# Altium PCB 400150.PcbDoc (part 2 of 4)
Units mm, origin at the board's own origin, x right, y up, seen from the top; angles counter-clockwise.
Board outline 101.6 x 63.5 mm, 4 copper layers (Top Layer, Mid-Layer 1, Mid-Layer 2, Bottom Layer), stack 1.582 mm thick; 248 components, 179 nets, 1093 pads, 875 vias.
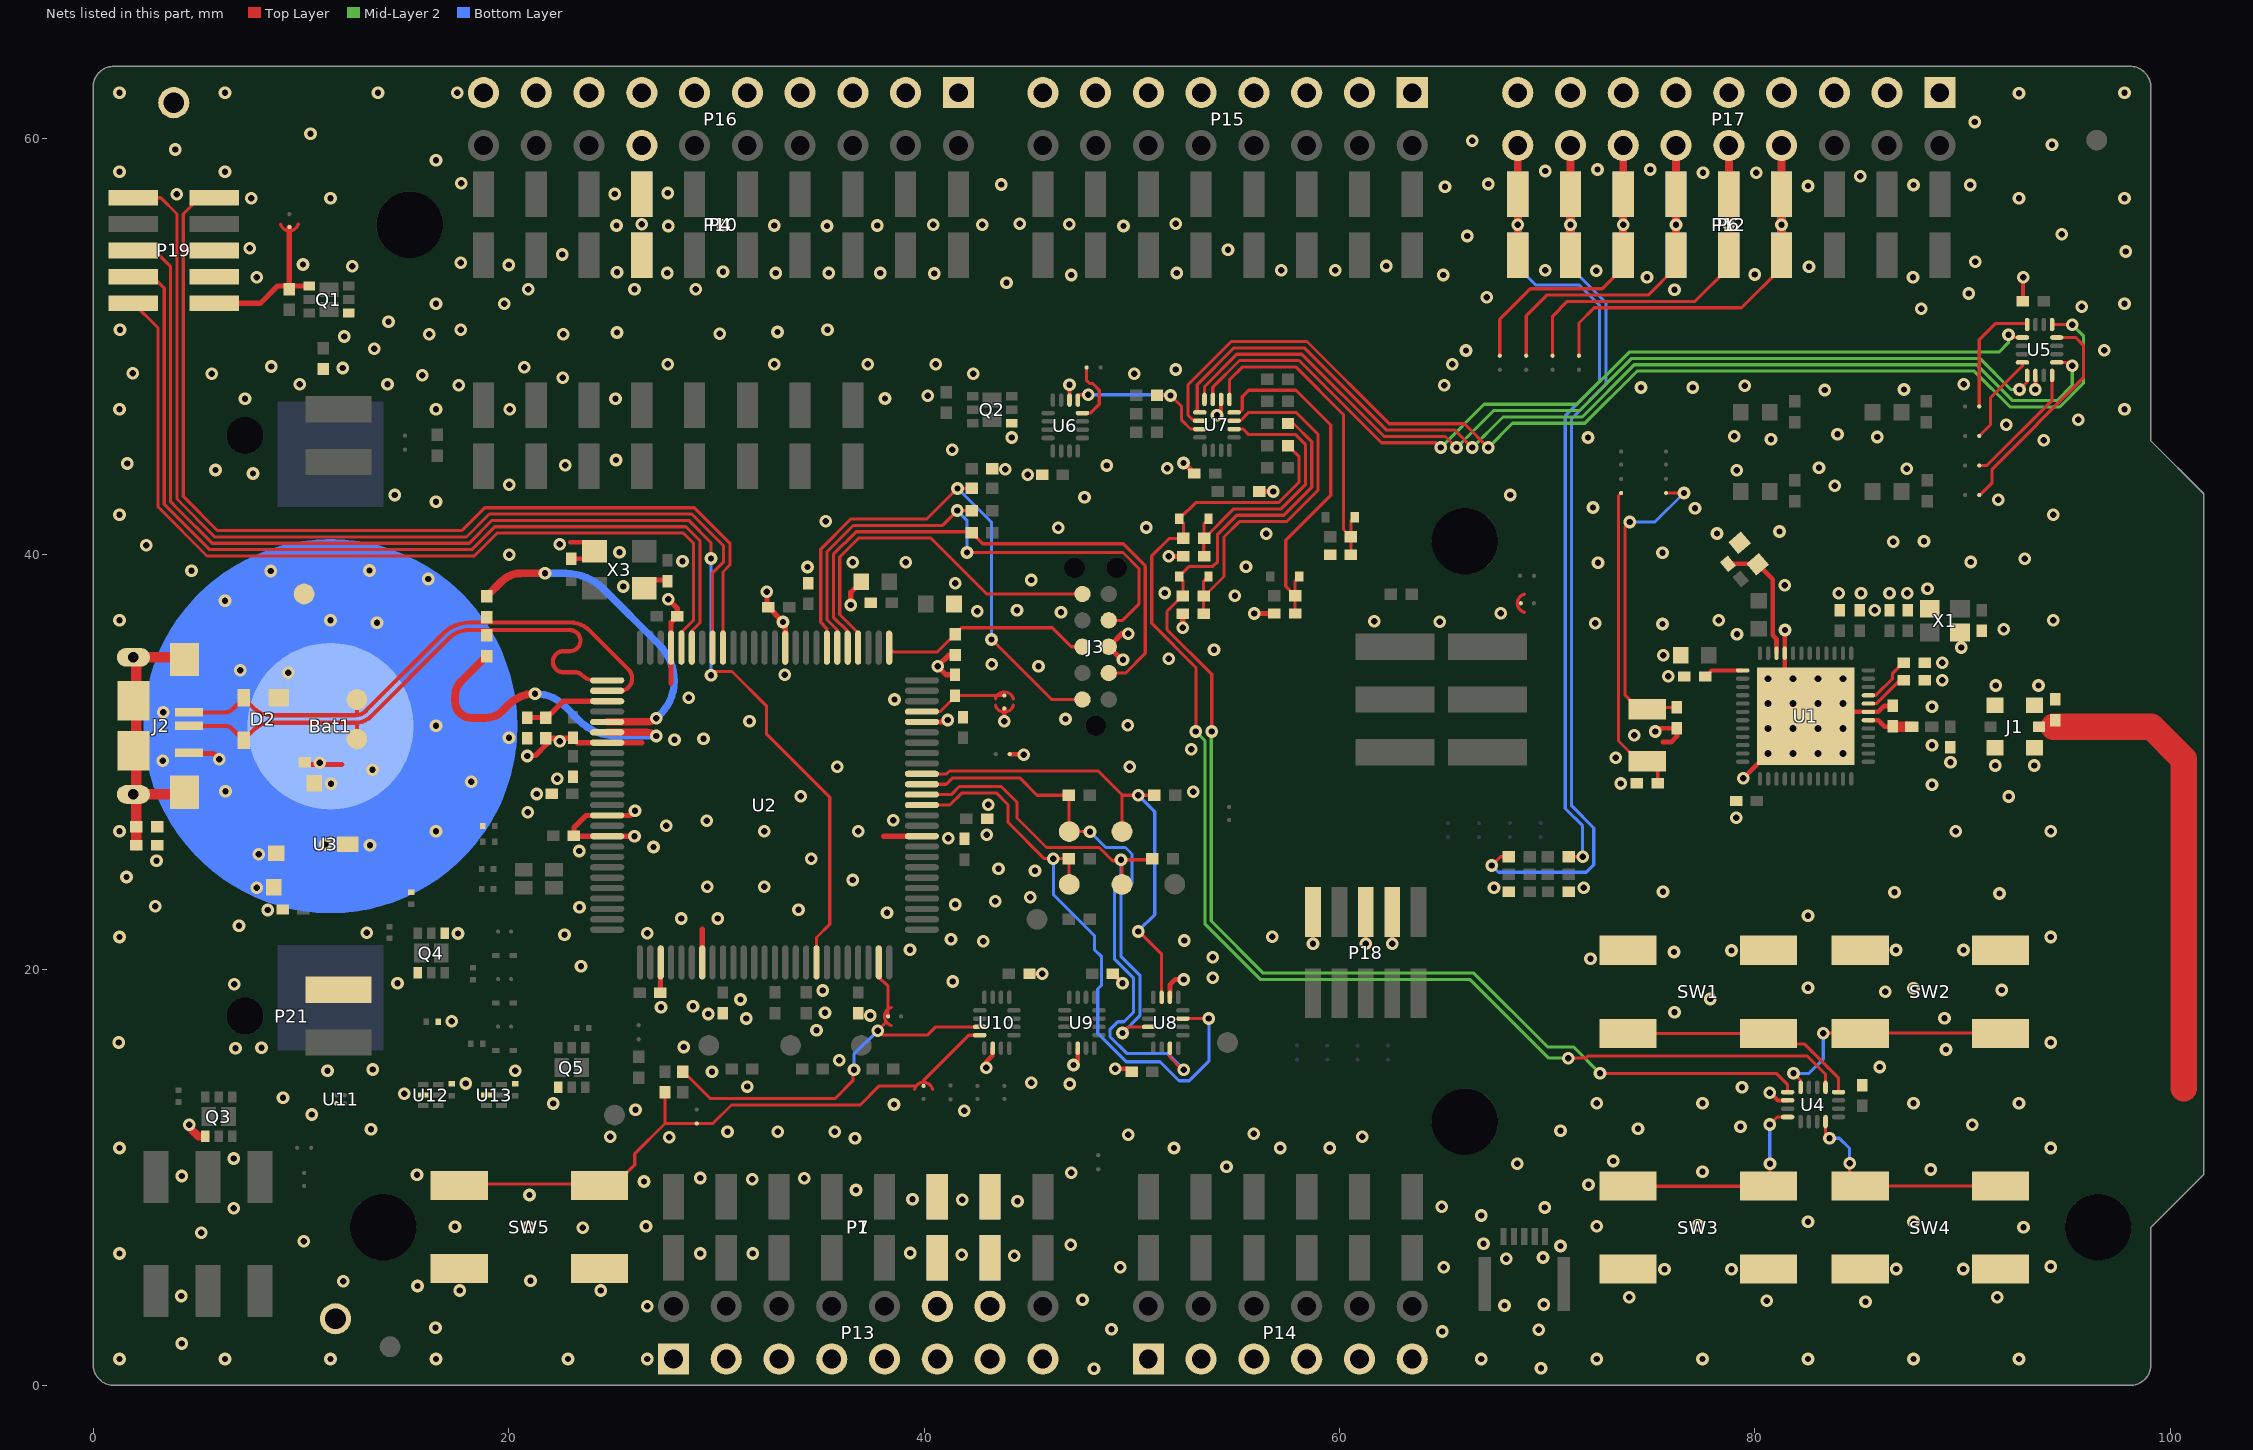
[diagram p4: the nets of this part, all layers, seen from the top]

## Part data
Bat1: library part "Bat Holder CR2032 SMD", "Bat Holder CR2032 SMD", 2nd source part number=165-0693, Manufacturer=Comfortable, Manufacturer Part Number=BC-2001, Supplier part number="BC-2001/T & R"
C1 C2 C11 C12 C52 C53: library part C0402-12p, "Capacitor, NP0, ±2%", Part number IPS=00000002398
C3: library part C0402-0.8p, "Capacitor, NP0, ±5%", Part number IPS=00000007782
C4 C5 C8 C14 C18 C19 C21 C24 C25 C26 C27 C28 C29 C32 C34 C35 C36 C38 C39 C40 C41 C44 C45 C46 C47 C54 C55: library part C0402-100n, "Capacitor, X7R, ±10%", Part number IPS=00000005296
C6 C13: library part C0402-N.C., "Not mounted"
C7: library part C0402-100p, "Capacitor, NP0, ±5%", Part number IPS=00000002361
C9: library part C0603-4µ7, "Capacitor, X5R, ±10%", Part number IPS=00000007783
C10 C16 C17: library part C0603-1µ0, "Capacitor, X7R, ±10%", Part number IPS=00000000616
C15: library part C0402-1.2p, "Capacitor, NP0, ±0.1pF", Part number IPS=00000005410
C20 C31 C33: library part C0603-10µ, "Capacitor, X5R, ±20%", Part number IPS=00000007785
C22 C23: library part C0402-18p, "Capacitor, NP0, ±5%"
C30: library part C0402-10n, "Capacitor, X7R, ±10%", Part number IPS=00000007784
C37: library part C0402-10p, "Capacitor, NP0, ±2%", 2nd source part number=185-6064, Supplier part number=712-1252-1-ND
C42 C43: library part C0402-300p, "Capacitor, NP0, ±5%", Supplier part number=490-3234-1-ND
C48 C49 C50 C51: library part C0402-1µ0, "Capacitor, X5R, ±5%", Part number IPS=00000007786, Supplier part number=1276-1444-1-ND
C56 C57: library part C0201-100n, "Capacitor, X5R, ±10%", Part number IPS=00000001248
D1 D7 D8: "20V schottky barrier diode, Vf 350 mV @ 100 mA, Ir 2.0 µA @ 10 V, If 500 mA", Manufacturer="ON Semiconductor", Part number IPS=N.A., Supplier Part Number 1=NSR0620P2T5GOSCT-ND
D2: "Ultra low capacitance double rail-to-rail ESD protection diode", 2nd source part number=152-4157, Manufacturer=NXP, Supplier part number=568-4140-1-ND
D3 D4 D5 D6: "Diode Schottky Vf=0.38, Vr=40V, If=200mA, Ir=500nA", 2nd source part number=873-4097, Manufacturer=NXP, Supplier part number=568-5973-1-ND
Fid1 Fid2: library part Fid-Mark, "Fiducial Mark"
J1: "Coaxial Connector with Switch", 2nd source part number=81-MM8130-2600RA2, Manufacturer=Murata, Supplier part number=490-4981-1-ND
J2: library part USB-Micro-B-RA-SMD-PiP, "MicroUSB-B-SMT", 2nd source part number=609-4616-1-ND, Manufacturer="Allen Creations Corp.", Manufacturer Part Number=AJU55-BS2111-L, Part number IPS=00000007790
J3: library part TC2050-IDC-NLFP, "CBL PLUG-OF-NAILS 10-PIN", Manufacturer="Tag-Connect LLC", Supplier part number=TC2050-IDC-NL-ND
L1: library part L0402-3n9, "Inductor, 170mA, ±0.1nH", Manufacturer=Murata, Manufacturer Part Number=LQP15MN3N9B02D, Part number IPS=00000007793, Supplier part number=490-1131-1-ND
L2: library part L0603-10µ, "Inductor, 80mA, ±10%", 2nd source part number=178-6105, Manufacturer="Taiyo Yuden", Manufacturer Part Number=LBMF1608T100K, Part number IPS=00000007794, Supplier part number=587-1714-1-ND
L3: library part L0402-15n, "Inductor, 320mA, ±5%", 2nd source part number=658-1328, Manufacturer="Taiyo Yuden", Manufacturer Part Number=HK100515NJ-T, Part number IPS=00000003215, Supplier part number=587-1521-1-ND
LD5: library part LTST-C195KGJRKT, "Ultra bright AlInGaP Bi-Color LED", 2nd source part number=859-LTST-C195KGJRKT, Manufacturer="Lite-On Inc", Supplier part number=160-1452-1-ND
LED1 LED2 LED3 LED4: library part "LG L29K Smartled Green", "LED SMARTLED GREEN 570NM 0603", 2nd source part number=720-LGL29KG2J124Z, Manufacturer=Osram, Manufacturer Part Number="LG L29K-G2J1-24-Z", Supplier part number=475-2709-1-ND
P1 P3: library part "Socket 1x8 SMD", "Socket 1x8, 2.54mm (100mil), SMD", 2nd source part number=SSM-108-F-SV-P-TR, Manufacturer=W-CON, Manufacturer Part Number=2171-108MS0CUNR1
P2: library part "Socket 1x6 SMD", "Socket 1x6, 2.54mm (100mil), SMD", 2nd source part number=SSM-106-F-SV-P-TR, Manufacturer=W-CON, Manufacturer Part Number=2171-106MS0CUNR1
P4: library part "Socket 1x10 SMD", "Socket 1x10, 2.54mm (100mil), SMD", 2nd source part number=SSM-110-F-SV-P-TR, Manufacturer=W-CON, Manufacturer Part Number=2171-110MS0CUNR1
P5: library part "Pin Header 2x3 SMD", "Pin Header 2x3, 2.54mm (100mil) SMD", 2nd source part number=TSM-103-01-L-DV, Manufacturer=W-CON, Manufacturer Part Number=1125-1203S0M116R1
P6: library part "Socket 1x9 SMD", "Socket 1x9, 2.54mm (100mil), SMD", 2nd source part number=SSM-109-L-SV, Manufacturer=W-CON, Manufacturer Part Number=2171-109MS0CUNR1
P7 P9: library part "Pin List 1x8 SMD, N.C.", "Pin List 1x8, 2.54mm (100mil), SMD", Manufacturer=W-CON, Manufacturer Part Number=1125-1108S0M116R2, Part number IPS=N.A.
P8: library part "Pin List 1x6 SMD, N.C.", "Pin List 1x6, 2.54mm (100mil), SMD", Manufacturer=W-CON, Manufacturer Part Number=1125-1106S0M116R2, Part number IPS=N.A.
P10: library part "Pin List 1x10 SMD, N.C.", "Pin List 1x10, 2.54mm (100mil), SMD", Manufacturer=W-CON, Manufacturer Part Number=1125-1110S0M116R2, Part number IPS=N.A.
P11: library part "Socket 2x3 SMD Bottom, N.C.", "Socket 2x3, 2.54mm (100mil), SMD", Manufacturer=W-CON, Manufacturer Part Number=2171-203MS0CUNR1, Part number IPS=N.A.
P12: library part "Pin List 1x9 SMD, N.C.", "Pin List 1x9, 2.54mm (100mil), SMD", Manufacturer=W-CON, Manufacturer Part Number=1125-1109S0M116R2, Part number IPS=N.A.
P13 P15: library part "Pin Header 2x8, N.C.", "Pin Header 2x8, 2.54mm (100mil)"
P14: library part "Pin Header 2x6, N.C.", "Pin Header 2x6, 2.54mm (100mil)"
P16: library part "Pin Header 2x10, N.C.", "Pin Header 2x10, 2.54mm (100mil)"
P17: library part "Pin Header 2x9, N.C.", "Pin Header 2x9, 2.54mm (100mil)"
P18 P19: library part "Pin Header 2x5 SMD, 1.27mm, KS", "Pin Header 2x5, 1.27mm (50mil), SMD, Keying Shroud", 2nd source part number=FTSH-105-01-F-DV-K, Manufacturer=W-CON, Manufacturer Part Number=3132-10MS0BK00R1
P20: library part "Pin List 1x8 SMD", "Pin List 1x8, 2.54mm (100mil), SMD", Manufacturer=W-CON, Manufacturer Part Number=1125-1108S0M116R2, Part number IPS=N.A.
P21 P22: library part "Pin List Ang 1x2 SMD, 2.54mm", "Pin List 1x2, 2.54mm (100mil), Right Angled, SMD", 2nd source part number=TSM-102-01-L-SH-A, Manufacturer=W-CON, Manufacturer Part Number=1125B-1102S0Z135R2
P23: library part FPC_05P-0.5mm-RA-SMD, "0.5mm FPC, 5P,Right Angle SMT,Double Contact,H=1.2mm,White, Tin plated", 2nd source part number=WM9836CT-ND, Manufacturer=W-CON, Manufacturer Part Number=5141-05RZDNWR01, Part number IPS=00000007792
P24: library part "Socket 1x8 SMD, N.C.", "Socket 1x8, 2.54mm (100mil), SMD", Manufacturer=W-CON, Manufacturer Part Number=2171-108MS0CUNR1, Part number IPS=N.A.
Q1 Q2 Q3 Q5: "Dual N & P Ch MOFET, 11.6A/9A, 90mOhm max, 6.25W", Manufacturer="Taiwan Semiconductor", Part number IPS=N.A., Supplier Part Number 1=TSM2537CQRFGCT-ND
Q4: "Dual N Ch MOFET, 5.8A, 55mOhm max, 620mW", Manufacturer="Taiwan Semiconductor", Part number IPS=N.A., Supplier Part Number 1=TSM250N02DCQRFGCT-ND
R1 R2 R3 R4: library part R0402-220, "Resistor, ±1%, 0.063W", Supplier part number=173-8841, Value Ohm=220
R5 R8 R9 R10 R11 R12: library part R0402-10k, "Resistor, ±1%, 0.063W", Part number IPS=00000002093, Supplier part number=173-8864, Value Ohm=10000
R6 R27 R28 R37: library part R0402-N.C., "Not mounted"
R7 R18 R25 R26 R38 R52 R53 R54 R55 R56 R57 R58 R59: library part R0402-0R, "Resistor, ±5%, 0.063W", Supplier part number=146-9661, Value Ohm=0
R13 R14: library part R0402-39R, "Resistor, ±1%, 0.063W", Part number IPS=00000000821, Supplier part number=173-8831, Value Ohm=39
R15 R16: library part R0402-150, "Resistor, ±1%, 0.063W", Supplier part number=173-8839, Value Ohm=150
R17: library part R0402-6k8, "Resistor, ±1%, 0.063W", Supplier part number=173-8862, Value Ohm=6800
R19 R20: library part R0201-220, "Resistor, ±1%, 0.05W", Part number IPS=00000000863
R21 R22 R23 R24 R29 R30: library part R0402-4k7, "Resistor, ±1%, 0.063W", Part number IPS=00000003433, Supplier part number=173-8858, Value Ohm=4700
R31 R32: library part R0402-12k, "Resistor, ±1%, 0.063W", Supplier part number=173-8865, Value Ohm=12000
R33 R34 R35 R36: library part R0402-100k, "Resistor, ±1%, 0.063W", Part number IPS=00000003667, Supplier part number=173-8877, Value Ohm=100000
R39: library part R0402-1M0, "Resistor, ±1%, 0.063W", Part number IPS=00000006807, Value Ohm=1000000
R40 R41 R42 R43: library part R0402-18k, "Resistor, ±1%, 0.063W", Part number IPS=00000003300, Supplier part number=173-8867, Value Ohm=18000
R44: library part R0201-33k, "Resistor, ±1%, 0.05W", Part number IPS=N.A.
R45: library part R0201-47k, "Resistor, ±1%, 0.05W", Part number IPS=N.A.
R46 R47 R48 R60: library part R0201-1M0, "Resistor, ±1%, 0.05W", Part number IPS=N.A.
R49: library part R0201-100k, "Resistor, ±1%, 0.05W", Part number IPS=N.A.
R50 R51: library part R0201-220k, "Resistor, ±1%, 0.05W", Part number IPS=N.A.
SB1 SB2 SB5 SB6 SB7 SB8 SB9 SB13 SB14 SB15 SB16 SB19 SB30 SB31 SB34: library part "Solderbridge Shorted", "Shorted Solderbridge"
SB20 SB21 SB22 SB23 SB24 SB25 SB26 SB27 SB29 SB36 SB41: library part "Solderbridge Shorted", "Shorted Solderbridge", Part number IPS=N.A.
SB35: library part "Solderbridge Shorted Power", "Shorted Solderbridge Power"
SW1 SW2 SW3 SW4 SW5: library part Switch-PB-6.2x6.3mm-SMD, "Tactile Switch, SPNO, SMD, 160gf, 6.2x6.3x2.5mm", 2nd source part number=688-SKHUALE010, Manufacturer=Dailywell, Manufacturer Part Number=TS604VM1-025BR-R, Part number IPS=00000007812
SW6: library part Switch-Slide-DPDT-8.5x3.6mm, "SMD slide Switch (ON-ON)", Manufacturer=Dailywell, Manufacturer Part Number=SS206VM-G2-LLR-R, Part number IPS=N.A.
TP1 TP2 TP3 TP4 TP5 TP6 TP7 TP8 TP9 TP10 TP11 TP14 TP15 TP20 TP21: library part TP_SMD_Ø1.0MM, "1.0mm circular SMD testpad", Manufacturer="Nordic Semiconductor"
TP12 TP13: library part "Testpoint TH", "Testpoint, through hole"
U1: "Multi-protocol Bluetooth Low Energy, ANT and 2.4GHz proprietary system-on-chip", Manufacturer="Nordic Semiconductor", Part number IPS=N.A.
U2: "IC MCU 32bit 128kB flash 100LQFP", 2nd source part number=184-1662, Manufacturer=Atmel, Supplier part number=ATSAM3U2CA-AU-ND
U3: "300mA, Low Quiescent Current, Fast Transient Low Dropout Linear Regulator", Manufacturer="Diodes Incorporated", Supplier part number=AP7333-33SAG-7DICT-ND
U4 U5 U6 U10: library part NX3DV2567GU, "Low-ohmic four-pole double-throw analog switch", 2nd source part number=771-NX3DV2567GU115, Manufacturer="NXP Semiconductors", Part number IPS=00000007816, Supplier part number=568-5206-1-ND
U7: library part PCAL6408AHK, "8-bit I2C-bus I/O expander with interrupt output", 2nd source part number=771-PCAL6408AHKX, Manufacturer="NXP Semiconductors", Supplier part number=568-9944-1-ND
U8 U9: "Data / Audio Low-Voltage Dual DPDT Analog Switch", 2nd source part number=512-FSA2466UMX, Manufacturer="Fairchild Semiconductor", Supplier part number=FSA2466UMXCT-ND
U11: "Semtech, 2A Low Vin, Very Low Ron, Load Switch, 4DSBGA", 2nd source part number=947-SC728CSTRT, Manufacturer="Semtech Corporation", Supplier part number=SC728CSTRTCT-ND
U12 U13: "Single 3-input AND gate", Manufacturer="ON Semiconductor", Part number IPS=N.A., Supplier Part Number 1=NC7SV11L6XCT-ND
X1: library part XTAL_SMD2016_32MHz_8pF_Epson, "XTAL SMD 2016, 32MHz, Cl=8pF, Tol: ±10ppm, Stab: ±10ppm", Manufacturer="Epson Toyocom", Manufacturer Part Number=Q22FA12800025, Supplier part number=171-2806
X2: library part "XTAL_FC-135 32.768k", "XTAL SMD 3215, 32.768kHz, 9pF, ±20ppm", 2nd source part number=127-8037, Manufacturer="Epson Toyocom", Manufacturer Part Number="FC-135 32.768KHZ ±20PPM,9.0PF", Supplier part number="FC-135 32.7680KA-AC-ND"
X3: library part XTAL_SMD3225_12MHz_18pF_TXC, "XTAL SMD 3225, 12MHz, Cl=18pF, Tol: ±30ppm, Stab: ±30ppm", 2nd source part number=184-2056, Manufacturer="TXC Corporation", Manufacturer Part Number=7M-12.000MAAJ-T, Supplier part number=887-1121-1-ND

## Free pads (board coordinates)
  round 3.2 hole 3.2: 1(13.97,7.61) 1(15.24,55.87) 1(66.04,12.69) 1(66.04,40.63) 1(96.52,7.61)

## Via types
v1: diameter 0.61, hole 0.305, Top Layer to Bottom Layer, tented both sides, 836 vias
v2: diameter 0.61, hole 0.305, Top Layer to Bottom Layer, 23 vias
v3: diameter 0.66, hole 0.33, Top Layer to Bottom Layer, tented both sides, 16 vias

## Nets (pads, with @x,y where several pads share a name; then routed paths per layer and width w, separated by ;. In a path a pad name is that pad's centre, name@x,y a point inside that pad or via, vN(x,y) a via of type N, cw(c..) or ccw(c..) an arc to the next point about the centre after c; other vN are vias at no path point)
ANT: C15.1 J1.3 | length 22.7
  Top Layer w1.27: 94.383,31.703 99.072,31.703 100.632,30.144 100.632,14.302
BOOT/RESET: R5.1 SB36.2 SB42.1 SW5.2 U10.4 | length 29.7
  Top Layer w0.152: SW5.2@17.631,9.61 17.714,9.693 24.298,9.693 SW5.2@24.381,9.61 25.078,9.61 26.073,10.606 26.073,11.138 27.532,12.597 ; R5.1@27.532,14.101 27.532,12.597 ; 39.626,14.409 37.854,14.409 36.935,13.491 30.732,13.491 29.838,12.597 SB36.2@29.063,12.597 27.532,12.597 ; SB42.1@39.98,14.409 39.98,14.584 39.98,14.681 42.148,16.85 U10.4@42.679,16.85
BUTTON1': SW1.2 U4.16 | length 11.7
  Top Layer w0.152: SW1.2@73.892,16.937 80.642,16.937 81.145,16.434 82.364,16.434 84.026,14.771 U4.16@84.026,14.099
BUTTON1_EXT: C48.1 D3.3 R40.1 U7.2 | length 13.5
  Top Layer w0.152: C48.1@53.465,39.898 53.465,40.761 R40.1@53.484,40.761 ; D3.3@53.69,41.701 53.484,41.495 R40.1@53.484,40.761 ; U7.2@54.925,46.028 55.365,46.028 55.632,45.761 57.886,45.761 58.36,45.288 58.36,43.346 57.197,42.184 54.907,42.184 R40.1@53.484,40.761
BUTTON2': SW2.2 U4.4 | length 12.3
  Top Layer w0.152: v1(81.856,15.011) 82.195,14.672 U4.4@82.195,14.338 ; v1(83.29,16.948) 91.809,16.948 SW2.2@91.818,16.94
  Bottom Layer w0.152: v1(81.856,15.011) 82.601,15.011 83.29,15.7 v1(83.29,16.948)
BUTTON2_EXT: C49.2 D4.3 R41.1 U7.3 | length 18
  Top Layer w0.152: C49.2@53.461,37.129 R41.1@53.461,37.993 ; D4.3@53.692,38.932 53.461,38.701 R41.1@53.461,37.993 ; U7.3@54.925,46.428 55.232,46.428 55.632,46.828 57.906,46.828 58.969,45.765 58.969,43.094 57.45,41.574 55.18,41.574 54.44,40.834 54.44,38.932 53.5,37.993 R41.1@53.461,37.993
BUTTON3': SW3.2 U4.8 | length 10.6
  Top Layer w0.152: SW3.2@73.889,9.581 SW3.2@80.639,9.581 ; v1(80.713,12.548) 81.078,12.913 U4.8@81.57,12.913 ; SW3.2@80.722,9.663 v1(80.722,10.659)
  Bottom Layer w0.152: v1(80.713,12.548) 80.713,10.668 v1(80.722,10.659)
BUTTON3_EXT: C50.2 D5.3 R42.1 U7.4 | length 17.3
  Top Layer w0.152: U7.4@54.925,46.828 55.193,46.828 55.32,46.955 55.32,47.582 55.632,47.895 57.906,47.895 59.579,46.222 59.579,42.841 57.412,40.674 57.412,38.459 R42.1@57.861,38.01 ; C50.2@57.861,37.147 R42.1@57.861,38.01 ; D5.3@58.061,38.932 57.861,38.732 R42.1@57.861,38.01
BUTTON4': SW4.2 U4.12 | length 10.8
  Top Layer w0.152: U4.12@83.395,12.688 83.395,12.075 v1(83.583,11.887) ; v1(84.557,10.684) 84.557,10.074 85.04,9.592 SW4.2@91.79,9.592
  Bottom Layer w0.152: v1(83.583,11.887) 84.065,11.887 84.557,11.395 v1(84.557,10.684)
BUTTON4_EXT: C51.1 D6.3 R43.1 U7.5 | length 15.6
  Top Layer w0.152: U7.5@54.7,47.453 54.7,48.388 55.335,49.022 57.886,49.022 60.192,46.717 60.192,41.191 R43.1@60.548,40.835 ; C51.1@60.548,39.972 R43.1@60.548,40.835 ; D6.3@60.728,41.783 60.548,41.603 R43.1@60.548,40.835
D17: P6.4 P12.4 P17.8 SB13.1 | length 21
  Top Layer w0.152: SB13.1@71.526,49.555 71.526,51.13 72.263,51.867 79.35,51.867 81.28,53.797 P6.4@81.28,54.405
  Top Layer w0.381: P6.4@81.28,54.651 v1(81.28,55.87) P6.4@81.28,57.335 P17.8@81.28,59.68
  Bottom Layer w0.381: P12.4@81.28,54.405 v1(81.28,55.87) P12.4@81.28,57.335
D18: P6.5 P12.5 P17.10 SB14.1 | length 20.2
  Top Layer w0.152: SB14.1@70.256,49.555 70.256,51.46 70.968,52.172 77.114,52.172 78.74,53.797 P6.5@78.74,54.405
  Top Layer w0.381: P6.5@78.74,54.405 v1(78.74,55.87) P6.5@78.74,57.335 P17.10@78.74,59.68
  Bottom Layer w0.381: P12.5@78.74,54.405 v1(78.74,55.87) P12.5@78.74,57.335
D19: P6.6 P12.6 P17.12 SB15.1 | length 18.7
  Top Layer w0.152: SB15.1@68.986,49.555 68.986,51.486 69.977,52.476 74.854,52.476 76.2,53.823 P6.6@76.2,54.405
  Top Layer w0.381: P6.6@76.2,54.6 v1(76.2,55.87) P6.6@76.2,57.335 P17.12@76.2,59.68
  Bottom Layer w0.381: P12.6@76.2,54.405 v1(76.2,55.87) P12.6@76.2,57.335
D20: P6.7 P12.7 P17.14 SB16.1 | length 17.2
  Top Layer w0.152: SB16.1@67.716,49.555 67.716,51.308 69.19,52.781 72.644,52.781 73.66,53.797 P6.7@73.66,54.405
  Top Layer w0.381: P6.7@73.66,54.701 v1(73.66,55.87) P6.7@73.66,57.335 P17.14@73.66,59.68
  Bottom Layer w0.381: P12.7@73.66,54.405 v1(73.66,55.87) P12.7@73.66,57.335
D21: P6.8 P12.8 P17.16 R27.1 | length 45.6
  Top Layer w0.152: v1(67.33,25.019) 67.752,25.441 R27.1@68.152,25.441
  Top Layer w0.381: P6.8@71.12,54.405 v1(71.12,55.87) P6.8@71.12,57.335 P17.16@71.12,59.68
  Bottom Layer w0.152: v1(67.33,25.019) 67.654,24.695 71.885,24.695 72.238,25.048 72.238,26.822 71.171,27.889 71.171,46.534 72.822,48.185 72.822,52.121 71.12,53.823 P12.8@71.12,54.405
  Bottom Layer w0.381: P12.8@71.12,54.405 v1(71.12,55.87) P12.8@71.12,57.335
D22: P6.9 P12.9 P17.18 R28.1 | length 41.7
  Top Layer w0.152: R28.1@71.032,25.441 v1(71.704,25.441)
  Top Layer w0.381: P6.9@68.58,54.405 v1(68.58,55.87) P6.9@68.58,57.335 P17.18@68.58,59.68
  Bottom Layer w0.152: P12.9@68.58,54.405 68.58,53.823 69.444,52.959 71.547,52.959 72.517,51.989 72.517,48.311 70.866,46.66 70.866,27.762 71.704,26.924 v1(71.704,25.441)
  Bottom Layer w0.381: P12.9@68.58,54.405 v1(68.58,55.87) P12.9@68.58,57.335
DEC1: C4.1 U1.1 | length 1.9
  Top Layer w0.203: C4.1@77.605,34.11 77.906,34.411 U1.1@79.41,34.411
DEC2: C6.1 U1.32 | length 2.2
  Top Layer w0.152: U1.32@85.46,32.811 85.846,32.811 86.973,33.938 C6.1@87.235,33.938
DEC3: C7.1 U1.33 | length 2.4
  Top Layer w0.152: U1.33@85.46,33.211 85.815,33.211 86.626,34.022 86.626,34.273 C7.1@87.11,34.758
DEC4: C10.2 L3.1 U1.46 | length 6
  Top Layer w0.229: L3.1@78.701,39.54 C10.2@80.109,39.54 ; C10.2@80.126,39.522 80.86,38.789 80.86,36.103 81.035,35.928 U1.46@81.035,35.267
DFSD_N: R14.1 U2.80 | length 16.4
  Top Layer w0.35: 20.574,39.08 v1(21.758,39.08) ; U2.80@24.749,31.932 26.635,31.932 ; 26.678,31.932 ccw(c26.678,32.553) v1@27.117,32.114
  Top Layer w0.381: R14.1@18.949,37.979 19.68,38.71 cw(c20.574,37.817) 20.574,39.08
  Bottom Layer w0.35: v1(21.758,39.08) 22.763,39.08 cw(c22.763,36.54) 24.559,38.336 27.262,35.633 cw(c25.528,33.899) 27.981,33.899 cw(c25.751,33.899) 27.328,32.322 v1(27.117,32.112)
DFSD_P: R13.1 U2.81 | length 16.3
  Top Layer w0.35: U2.81@24.749,31.43 26.66,31.43 ; 26.678,31.43 cw(c26.678,30.809) v1@27.117,31.248
  Top Layer w0.381: R13.1@18.949,35.111 17.724,33.886 ccw(c18.448,33.162) 17.424,33.162 17.424,32.934 ccw(c18.237,32.934) 18.237,32.121 18.888,32.121 ccw(c18.888,33.273) 19.703,32.458 20.01,32.765 cw(c21.275,31.5) v1(21.275,33.289)
  Bottom Layer w0.35: v1(21.275,33.289) cw(c21.275,31.266) 22.706,32.697 23.411,31.992 ccw(c25.207,33.788) 25.207,31.248 v1@27.117,31.248
  other v1: 27.117,31.251
DHSD_N: D2.2 J2.2 R14.2 TP2.1 U2.77 | length 28.6
  Top Layer w0.203: J2.2@4.619,32.387 6.34,32.387 ccw(c6.34,32.895) 6.699,32.536 D2.2@7.234,33.072 ; D2.2@7.244,33.095 7.244,33.089 7.754,32.58 ccw(c8.552,33.377) 8.552,32.249 12.645,32.249 ccw(c12.645,32.925) 13.123,32.447 16.872,36.196 ; 12.7,32.304 TP2.1@12.7,33.01 ; 16.869,36.199 cw(c18.105,34.962) 18.095,36.711 22.977,36.711 cw(c22.977,35.405) 23.9,36.328 25.773,34.456 ; 18.096,36.711 cw(c18.105,34.962) 18.105,36.711 ; U2.77@24.749,33.43 U2.77@25.344,33.43 ; 25.773,34.456 cw(c25.344,34.027) 25.344,33.421 ccw(c25.344,34.027) 25.773,34.456
  Top Layer w0.35: D2.2@7.244,33.095 cw(c7.211,33.095) 7.235,33.072 ccw(c7.211,33.095) D2.2@7.244,33.095
DHSD_P: D2.3 J2.3 R13.2 TP1.1 U2.76 | length 28
  Top Layer w0.203: J2.3@4.619,31.74 6.34,31.74 cw(c6.34,31.232) 6.699,31.591 D2.3@7.244,31.045 ; D2.3@7.244,31.051 7.754,31.561 ; TP1.1@12.7,31.105 12.7,31.83 ; 17.134,35.954 cw(c18.095,34.994) 17.139,35.96 cw(c18.095,34.994) 18.095,36.352 22.985,36.352 ; 17.144,35.965 13.376,32.196 cw(c12.639,32.934) 12.639,31.891 8.551,31.891 ; 22.642,34.318 cw(c22.642,34.826) 22.642,35.334 ; 22.647,34.318 23.25,34.318 cw(c23.25,33.971) 23.495,34.216 ccw(c24.187,34.908) 24.187,33.93 U2.76@24.749,33.93 ; 22.652,35.334 22.952,35.334 ccw(c22.952,35.842) 22.952,36.35 ; 7.754,31.561 cw(c8.551,30.763) 8.551,31.891 ; 7.754,31.561 cw(c8.551,30.763) 8.551,31.891
  Top Layer w0.35: D2.3@7.244,31.045 D2.3@7.244,31.051
EXT_GND_DETECT: P19.9 U2.67 | length 48.7
  Top Layer w0.152: P19.9@5.836,57.165 5.131,57.165 4.343,56.378 4.343,42.786 5.991,41.138 17.743,41.138 18.847,42.241 28.944,42.241 30.658,40.527 30.658,39.483 30.324,39.149 U2.67@30.324,35.505
EXT_RESET: P19.10 U2.68 | length 49.4
  Top Layer w0.152: P19.10@1.936,57.165 3.251,57.165 4.039,56.378 4.039,42.66 5.865,40.833 17.974,40.833 19.078,41.936 28.817,41.936 30.353,40.401 30.353,39.632 29.824,39.103 U2.68@29.824,35.505 U2.68@29.82,35.509
EXT_SWDCLK: P19.4 U2.70 | length 44.8
  Top Layer w0.152: P19.4@1.936,53.355 2.87,53.355 3.429,52.796 3.429,42.407 5.613,40.223 18.227,40.223 19.33,41.327 28.543,41.327 29.21,40.66 29.21,36.694 28.824,36.308 U2.70@28.824,35.505
EXT_SWDIO: P19.2 U2.71 | length 43
  Top Layer w0.152: P19.2@1.936,52.085 3.124,50.897 3.124,42.281 5.486,39.919 18.353,39.919 19.456,41.022 28.417,41.022 28.905,40.534 28.905,36.82 28.324,36.239 U2.71@28.324,35.505
EXT_SWO: P19.6 U2.18 | length 64.9
  Top Layer w0.152: P19.6@1.936,54.625 2.946,54.625 3.734,53.838 3.734,42.533 4.037,42.23 5.739,40.528 18.101,40.528 19.204,41.632 28.671,41.632 29.743,40.559 v1(29.743,39.8) ; v1(29.743,34.178) 29.921,34.356 30.759,34.356 32.41,32.705 32.41,31.359 35.458,28.311 35.458,22.189 34.824,21.555 U2.18@34.824,20.355
  Bottom Layer w0.152: v1(29.743,34.178) v1(29.743,39.8)
EXT_VTG: P19.1 Q1.4 R8.1 SB32.2 | length 7.9
  Top Layer w0.254: P19.1@5.836,52.085 8.052,52.085 8.88,52.913 R8.1@9.449,52.913 ; R8.1@9.449,52.763 R8.1@9.449,52.913 ; SB32.2@9.449,55.745 9.449,55.571 R8.1@9.449,52.913 ; Q1.4@10.404,52.913 R8.1@9.449,52.913
GND: Bat1.2 C1.2 C2.2 C3.1 C4.2 C5.2 C6.2 C7.2 C8.2 C9.2 C10.1 C11.1 C12.1 C13.2 C14.1 C15.2 C16.1 C17.1 C18.1 C19.1 C20.1 C21.1 C22.2 C23.2 C24.1 C25.1 C26.1 C27.1 C28.1 C29.1 C30.1 C31.1 C32.1 C33.1 C34.1 C35.1 C36.2 C37.1 C38.1 C39.1 C40.1 C41.1 C42.2 C43.1 C44.1 C45.1 C46.1 C47.1 C48.2 C49.1 C50.1 C51.2 C52.2 C53.2 C54.1 C55.1 C56.1 C57.1 D2.1 J1.2 J2.5 J3.3 P1.6 P1.7 P4.7 P7.6 P7.7 P10.7 P13.1 P13.3 P13.5 P13.7 P13.9 P13.11 P13.12 P13.13 P13.14 P13.15 P14.1 P14.3 P14.5 P14.7 P14.9 P14.11 P15.1 P15.3 P15.5 P15.7 P15.9 P15.11 P15.13 P15.15 P16.1 P16.3 P16.5 P16.7 P16.9 P16.11 P16.13 P16.14 P16.15 P16.17 P16.19 P17.1 P17.3 P17.5 P17.7 P17.9 P17.11 P17.13 P17.15 P17.17 P18.3 P18.5 P18.9 P19.3 P19.5 P21.1 Q1.1 Q2.1 Q3.1 Q4.1 Q4.4 Q5.1 R10.1 R11.1 R12.1 R17.1 R24.2 R38.1 R45.2 R50.2 R51.2 SB18.1 SB28.2 SB31.2 SW1.1 SW2.1 SW3.1 SW4.1 SW5.1 TP4.1 TP12.1 TP13.1 U1.31 U1.45 U1.49 U2.3 U2.7 U2.35 U2.46 U2.61 U2.72 U2.82 U2.89 U2.91 U3.3 U4.6 U5.6 U6.6 U7.6 U8.6 U9.6 U10.6 U11.B1 U12.2 U13.2 X1.2 X1.4 X3.2 X3.4 | length 71
  Top Layer w0.203: 22.962,40.579 23.715,40.579 X3.2@24.145,40.149 23.78,39.784 C22.2@23.028,39.784 ; U6.6@47.003,47.422 v1(47.003,48.158) ; v1(54.1,46.685) 54.3,46.885 U7.6@54.3,47.453 ; v1(58.725,21.26) P18.9@58.725,22.772 ; v1(61.265,21.26) P18.5@61.265,22.772 ; v1(62.535,21.26) P18.3@62.535,22.772 ; v1(80.713,14.072) 80.741,14.072 81.1,13.713 U4.6@81.57,13.713 ; C45.1@92.896,52.172 v1@92.896,53.331 ; v1(93.497,47.93) 93.501,47.933 U5.6@93.501,48.61
  Top Layer w0.229: v1(32.436,38.2) 32.436,37.529 C35.1@32.51,37.455 ; v1(43.002,15.291) 43.002,15.575 43.281,15.854 43.281,16.201 U10.6@43.304,16.225 ; v1(43.866,31.966) SB28.2@43.866,32.575 ; SB31.2@44.127,30.378 44.78,30.378 v1(44.806,30.353) ; C55.1@45.077,19.812 v1(45.695,19.812) ; v1(47.193,15.418) 47.396,15.621 U9.6@47.396,16.225 ; C54.1@49.09,19.812 49.094,19.816 v1(49.555,19.355) ; v1(49.2,15.24) 49.784,15.24 49.936,15.088 C14.1@49.995,15.088 ; U8.6@51.838,18.675 51.838,19.275 52.095,19.533 v1(52.502,19.533) ; v1(75.2,31.467) 75.36,31.627 C11.1@76.241,31.627 76.241,31.23 75.969,30.959 75.569,30.959 ; v1(79.438,29.211) 79.438,29.214 v3(80.635,30.411) U1.49@82.435,32.211 ; U1.49@81.435,34.411 U1.45@81.435,35.236 v1@81.435,36.352 ; U1.49@83.052,32.414 85.934,32.414 86.221,32.701 C3.1@86.634,32.701
  Top Layer w0.254: J2.5@4.746,30.44 4.746,30.406 5.803,30.406 v2(6.071,30.139) ; C21.1@10.193,29.987 10.193,29.886 11.966,29.886 ; v1@21.021,30.317 21.301,30.317 21.859,30.876 21.859,31.138 23.104,31.138 23.312,30.93 26.413,30.93 ; v1(26.06,26.431) v1(26.06,26.431) 23.174,26.43 C41.1@23.147,26.457 23.147,26.839 23.738,27.43 25.865,27.43 v1(26.086,27.65) ; X3.4@26.533,38.758 C23.2@27.651,38.758 ; C24.1@27.312,18.887 U2.3@27.312,20.343 ; v1(27.686,37.836) 28.125,37.397 C36.2@28.125,37.023 27.824,36.722 27.824,33.783 ; U2.7@29.324,20.355 29.324,21.948 ; C35.1@32.51,37.455 v1@33.17,36.794 ; U2.61@33.324,35.505 v1@33.324,36.585 ; v1(36.474,37.556) 36.474,38.165 C33.1@36.983,38.674 ; 38.051,26.43 U2.35@39.899,26.43 ; U2.46@39.899,31.93 41.049,31.93 v1(41.138,32.019) ; C30.1@41.494,34.196 41.07,34.196 v1(40.655,34.61) 41.197,35.151 R24.2@41.494,35.151 ; v1@49.555,36.21 J3.3@48.895,35.55 49.53,34.915 v1(49.581,34.915) ; v1(51.773,39.898) C48.2@52.484,39.898 ; v1(52.459,36.469) 52.459,37.127 C49.1@52.461,37.129 ; v1(52.492,44.393) 52.51,44.393 C47.1@53.018,43.885 ; v1(55.898,37.147) C50.1@56.861,37.147 ; R38.1@56.143,43.022 v1(56.81,43.022)
  Top Layer w0.381: v1(4.634,12.539) 4.634,12.412 5.071,11.975 Q3.1@5.406,11.975
  other v1: 48.184,0.787 69.698,0.813 1.27,1.26 6.35,1.26 11.43,1.26 16.51,1.26 22.86,1.26 26.67,1.26 66.827,1.26 72.39,1.26 77.47,1.26 82.55,1.26 87.63,1.26 92.71,1.26 4.267,2.007 64.948,2.591 69.596,2.667 49.022,2.692 16.485,2.769 26.67,3.8 67.945,3.835 69.825,3.886 85.319,4.013 80.569,4.064 47.625,4.115 73.939,4.242 91.669,4.242 4.242,4.293 17.653,4.562 24.435,4.562 15.621,4.775 12.04,5.004 21.057,5.029 75.642,5.581 78.867,5.581 86.792,5.592 90.018,5.592 49.454,5.679 65.017,5.679 94.234,5.715 68.021,6.096 69.799,6.147 44.348,6.238 41.808,6.289 1.27,6.34 29.235,6.34 31.75,6.34 39.345,6.365 70.637,6.706 47.066,6.756 66.929,6.807 10.142,6.926 5.203,7.336 23.571,7.584 92.928,7.598 20.951,7.628 17.424,7.635 26.619,7.645 72.39,7.661 77.254,7.709 82.55,7.864 87.63,7.864 66.827,8.169 6.777,8.526 69.875,8.56 64.922,8.585 44.501,8.854 41.834,8.931 39.446,8.956 21.006,9.159 36.728,9.398 71.984,9.652 26.518,9.804 31.725,9.921 34.239,9.957 29.235,9.972 4.267,10.074 15.596,10.135 47.092,10.236 77.47,10.278 88.465,10.386 54.559,10.516 68.555,10.668 73.177,10.795 6.777,10.913 1.27,11.42 52.032,11.42 57.15,11.42 59.538,11.42 94.234,11.42 36.678,11.887 27.738,11.93 24.891,11.956 61.098,11.956 49.823,12.051 55.873,12.099 30.541,12.2 32.96,12.2 35.697,12.2 70.637,12.243 13.376,12.322 74.371,12.344 79.299,12.446 90.458,12.537 10.531,13.03 41.935,13.208 26.111,13.259 38.557,13.513 22.149,13.564 72.39,13.579 77.47,13.579 87.63,13.579 92.71,13.579 9.144,13.832 14.98,14.037 79.375,14.351 31.496,14.376 47.015,14.503 17.938,14.528 45.161,14.554 29.794,15.088 11.283,15.144 20.32,15.144 13.469,15.197 86.004,15.316 35.916,15.646 89.194,16.162 6.858,16.225 8.108,16.241 28.432,16.283 1.245,16.5 94.234,16.5 34.823,17.094 17.272,17.516 31.445,17.653 89.12,17.668 37.419,17.795 29.616,17.871 35.23,17.932 76.124,17.95 27.342,18.196 28.88,18.237 31.166,18.567 77.851,18.593 86.263,18.949 35.128,18.999 91.881,19.023 87.63,19.116 82.55,19.141 6.792,19.294 14.656,19.345 41.377,19.431 53.899,19.609 23.485,20.165 72.085,20.523 53.899,20.599 76.098,20.853 78.867,20.93 86.789,20.948 90.04,20.948 39.324,20.97 42.85,21.377 52.527,21.412 41.3,21.463 1.27,21.58 56.769,21.59 94.234,21.58 22.694,21.692 17.566,21.748 13.17,21.782 26.685,21.758 7.026,22.12 28.321,22.469 30.074,22.469 82.55,22.596 38.217,22.748 8.407,22.875 33.962,22.895 23.419,23.002 2.999,23.063 41.504,23.139 43.434,23.292 45.11,23.495 91.772,23.669 75.573,23.749 86.716,23.739 67.437,23.952 71.755,23.952 29.566,23.993 32.309,23.993 36.576,24.323 1.611,24.467 45.339,24.765 43.586,24.867 3.058,25.245 34.569,25.349 23.409,25.72 26.975,25.908 41.163,26.33 43.028,26.492 1.27,26.66 32.309,26.66 36.83,26.66 89.662,26.66 94.234,26.66 27.584,26.939 29.54,27.168 38.522,27.193 79.099,27.324 20.93,27.584 43.096,27.94 34.064,28.356 92.209,28.337 21.361,28.463 52.955,28.576 88.519,28.906 73.546,28.963 22.342,29.2 35.816,29.778 49.91,29.765 91.567,29.835 93.447,29.835 89.408,29.987 73.304,30.201 20.894,30.292 52.857,30.607 88.519,30.8 22.469,31.003 27.991,31.079 29.388,31.115 74.193,31.293 49.81,31.765 31.598,31.968 46.812,32.07 88.519,32.654 38.583,33.01 28.677,33.086 91.589,33.684 93.647,33.684 89.013,33.938 75.831,34.122 33.289,34.204 45.508,34.61 43.256,34.712 89.013,34.777 51.773,34.976 75.577,35.138 53.957,35.408 89.928,35.513 79.133,36.153 49.835,36.17 81.444,36.352 91.973,36.398 75.551,36.64 72.314,36.678 33.213,36.744 64.821,36.754 61.671,36.779 1.27,36.82 78.257,36.83 94.361,36.82 67.759,37.16 46.592,37.216 42.57,37.262 44.475,37.313 85.762,37.309 54.966,37.998 51.587,38.139 84.035,38.13 85.102,38.13 86.473,38.13 87.337,38.13 88.302,38.333 25.527,38.445 81.432,38.506 41.504,38.598 45.161,38.76 4.739,39.207 34.392,39.385 55.499,39.395 72.441,39.599 36.566,39.614 39.116,39.614 90.385,39.628 28.372,39.665 92.992,39.783 20.041,39.98 75.551,40.069 25.339,40.096 2.565,40.427 22.469,40.477 86.651,40.603 88.138,40.63 56.472,40.996 78.168,41 81.178,41.097 46.464,41.275 50.698,41.29 35.277,41.595 1.27,41.9 94.361,41.9 77.114,42.215 72.199,42.254 16.51,42.535 91.71,42.621 47.729,42.748 14.529,42.85 68.216,42.85 83.845,43.297 20.041,43.348 44.991,43.835 7.696,43.891 79.121,44.044 5.893,44.059 43.917,44.094 87.3,44.12 51.714,44.145 83.083,44.171 48.796,44.272 22.733,44.287 1.646,44.373 25.171,44.541 41.362,45.038 93.896,45.491 80.772,45.542 44.221,45.618 71.958,45.618 85.877,45.644 79.006,45.683 83.973,45.771 92.096,46.227 95.56,46.483 1.27,46.98 16.51,46.98 20.066,46.98 97.79,46.98 7.315,47.488 25.146,47.488 38.125,47.498 40.185,47.623 83.363,47.904 87.173,47.93 74.516,48.031 77.005,48.031 79.502,48.108 17.602,48.133 65.049,48.133 9.957,48.184 14.173,48.184 90.043,48.184 22.606,48.504 15.85,48.616 5.715,48.682 42.377,48.696 50.114,48.692 1.908,48.713 52.121,48.895 12.012,48.964 20.752,48.997 8.585,49.037 27.661,49.149 32.791,49.149 37.287,49.149 40.564,49.149 65.43,49.149 66.091,49.809 96.814,49.815 13.529,49.893 12.09,50.485 16.18,50.597 22.631,50.597 30.175,50.622 25.222,50.673 32.944,50.698 1.295,50.8 17.704,50.8 35.357,50.8 14.224,51.196 88.011,51.816 95.728,51.918 16.51,52.06 19.787,52.06 97.79,52.06 67.081,52.375 90.297,52.553 76.124,52.73 20.955,52.756 26.06,52.756 29.007,52.756 43.967,53.076 7.874,53.33 74.803,53.34 87.605,53.34 92.905,53.34 47.092,53.442 64.999,53.442 79.985,53.467 40.488,53.518 27.635,53.543 32.868,53.543 35.408,53.543 37.897,53.543 52.172,53.543 25.222,53.569 30.328,53.594 72.365,53.645 57.201,53.67 59.792,53.67 69.901,53.67 82.601,53.848 12.471,53.863 62.255,53.873 20.015,53.924 10.109,53.95 17.704,54.026 90.602,54.077 22.581,54.432 97.841,54.575 54.635,54.661 7.544,54.737 66.142,55.321 94.768,55.411 27.686,55.804 35.331,55.804 49.606,55.804 25.197,55.829 30.328,55.829 32.791,55.829 37.744,55.829 40.437,55.855 42.799,55.855 26.416,55.88 46.99,55.88 44.602,55.905 52.121,55.905 7.62,57.14 11.43,57.14 92.71,57.14 97.79,57.14 4.037,57.335 25.121,57.343 27.661,57.394 65.075,57.699 82.55,57.724 87.63,57.775 90.368,57.775 43.713,57.8 67.158,57.826 17.729,57.861 85.065,58.191 77.495,58.369 80.061,58.369 1.27,58.41 6.35,58.41 69.901,58.445 72.415,58.522 74.955,58.522 16.51,58.969 3.962,59.487 94.296,59.715 66.396,59.908 10.465,60.249 90.576,60.808 92.71,62.194 1.27,62.22 6.35,62.22 13.716,62.22 17.526,62.22 97.79,62.22
  other v2: 7.874,23.942 7.976,25.568 13.335,25.999 11.171,26.032 16.51,26.66 6.375,28.6 11.454,28.949 18.212,29.058 13.452,29.632 10.915,29.964 3.348,30.061 20.02,31.168 16.51,31.74 3.375,32.391 9.398,34.29 7.087,34.417 13.665,36.703 11.43,36.82 6.35,37.77 16.129,38.811 8.56,39.192 13.31,39.218
  other v3: 81.835,30.411 83.035,30.411 84.235,30.411 80.635,31.611 81.835,31.611 83.035,31.611 84.235,31.611 80.635,32.811 81.835,32.811 83.035,32.811 84.235,32.811 80.635,34.011 81.835,34.011 83.035,34.011 84.235,34.011
IMCU_BOOT: R55.2 SB45.2 U2.24 U10.3 | length 20.5
  Top Layer w0.152: R55.2@28.396,15.101 28.413,15.101 29.709,13.805 35.725,13.805 36.576,14.656 36.576,15.138 v1(36.627,15.189) ; U2.24@37.824,20.355 37.824,19.644 38.27,19.198 SB45.2@38.27,17.755 ; 38.186,17.485 v1(37.77,17.069) 37.973,16.866 40.183,16.866 40.567,17.25 U10.3@42.679,17.25
  Bottom Layer w0.152: v1(36.627,15.189) 36.627,15.926 v1(37.77,17.069)
IMCU_CTS: R18.2 TP5.1 U2.38 U8.3 | length 29.9
  Top Layer w0.152: U2.38@39.899,27.93 41.247,27.93 41.831,28.514 43.47,28.514 44.044,27.94 44.044,27.102 45.796,25.349 v1(46.228,25.349) 46.82,25.349 46.896,25.273 R18.2@46.973,25.349 46.973,24.127 TP5.1@46.99,24.11 ; U8.3@52.463,17.65 v1(53.699,17.65)
  Bottom Layer w0.152: v1(46.228,25.349) 46.228,23.622 48.209,21.641 48.209,20.965 48.55,20.625 48.55,19.264 48.362,19.075 48.362,16.942 49.733,15.57 51.359,15.57 52.273,14.656 52.766,14.656 53.721,15.611 53.721,17.628 v1(53.699,17.65)
IMCU_RESET: J3.10 R23.1 U2.57 | length 26.9
  Top Layer w0.152: U2.57@35.324,35.505 35.324,36.424 35.027,36.722 35.027,40.247 36.477,41.697 40.14,41.697 v1(41.614,43.17) R23.1@42.295,43.17 R23.1@42.303,43.17 ; v1(43.252,35.899) 46.141,33.01 J3.10@47.625,33.01
  Bottom Layer w0.152: v1(41.614,43.17) 43.252,41.531 v1(43.252,35.899)
IMCU_RTS: R7.2 TP7.1 U2.39 U8.15 | length 29.7
  Top Layer w0.152: U2.39@39.899,28.43 41.316,28.43 41.705,28.819 43.724,28.819 44.475,28.067 44.475,27.305 45.898,25.883 48.438,25.883 49.073,25.248 v1@49.53,25.248 ; v1(49.479,25.298) v1@49.581,25.298 ; TP7.1@49.53,24.11 v1@49.53,25.248 ; R7.2@50.986,25.349 50.935,25.298 v1@49.581,25.298 ; U8.15@51.838,16.225 51.838,15.777 52.426,15.189 v1(52.502,15.189) ; v1@49.53,25.248 v1@49.581,25.298
  Bottom Layer w0.152: v1(49.479,25.298) 49.479,24.181 49.174,23.876 49.174,20.498 50.089,19.583 50.089,17.965 49.624,17.501 49.334,17.501 48.946,17.112 48.946,16.789 49.759,15.977 51.714,15.977 v1(52.502,15.189)
IMCU_RxD: R58.2 TP6.1 U2.40 U8.11 | length 23.7
  Top Layer w0.152: U2.40@39.899,28.93 41.071,28.93 41.377,29.235 44.602,29.235 45.441,28.397 R58.2@46.973,28.397 46.973,26.667 TP6.1@46.99,26.65 47.986,26.65 v1(47.991,26.645) ; v1(49.555,16.954) 49.555,16.967 49.838,17.25 U8.11@50.813,17.25
  Bottom Layer w0.152: v1(47.991,26.645) 48.753,25.883 49.7,25.883 50.013,25.57 50.013,24.155 49.479,23.622 49.479,20.65 50.394,19.736 50.394,17.78 49.555,16.942 v1(49.555,16.954)
IMCU_TCKS: J3.4 R22.1 U2.56 | length 26.9
  Top Layer w0.152: U2.56@35.824,35.505 35.824,36.355 35.331,36.848 35.331,40.12 36.603,41.392 40.894,41.392 v1(41.605,42.103) R22.1@42.295,42.103 ; v1(42.066,40.085) 42.067,40.084 49.576,40.084 50.343,39.317 50.343,37.603 49.56,36.82 J3.4@48.895,36.82
  Bottom Layer w0.152: v1(41.605,42.103) 42.066,41.642 v1(42.066,40.085)
IMCU_TDIS: J3.8 R24.1 U2.51 | length 10.3
  Top Layer w0.152: U2.51@38.324,35.505 38.533,35.296 40.638,35.296 R24.1@41.494,36.151 41.806,36.464 46.177,36.464 47.092,35.55 J3.8@47.625,35.55
IMCU_TDOS: J3.6 U2.54 | length 17.9
  Top Layer w0.152: U2.54@36.824,35.505 36.824,36.217 35.941,37.1 35.941,39.868 36.855,40.782 40.322,40.782 43.014,38.09 J3.6@47.625,38.09
IMCU_TMSS: J3.2 R21.1 U2.55 | length 27.3
  Top Layer w0.152: U2.55@36.324,35.505 36.324,36.286 35.636,36.974 35.636,39.994 36.729,41.087 42.245,41.087 42.829,40.503 49.588,40.503 50.648,39.443 50.648,35.227 49.7,34.28 J3.2@48.895,34.28
IMCU_TxD: R56.2 TP8.1 U2.41 U8.7 | length 24.4
  Top Layer w0.152: U2.41@39.899,29.43 39.899,29.428 41.087,29.428 41.224,29.566 48.387,29.566 49.555,28.397 ; TP8.1@49.53,26.65 49.53,28.372 49.555,28.397 ; v1@50.317,21.869 51.438,20.749 U8.7@51.438,18.675 ; R56.2@51.087,28.397 v1(50.317,28.397) 49.555,28.397
  Bottom Layer w0.152: v1@50.317,21.869 51.105,22.657 51.105,27.61 50.368,28.346 50.368,28.397 v1(50.317,28.397)
  other v1: 50.317,21.844
INT_EXT: R31.1 U6.5 U7.11 | length 7.8
  Top Layer w0.152: U6.5@47.403,47.422 47.403,47.58 47.498,47.676 v1(47.904,47.676) ; R31.1@51.214,47.645 v1(51.865,47.645) 52.399,47.111 52.399,46.457 52.827,46.028 U7.11@53.275,46.028
  Bottom Layer w0.152: v1(47.904,47.676) 51.834,47.676 v1(51.865,47.645)
IOEXP_IRQ: SB30.2 U6.4 | length 3.1
  Top Layer w0.152: U6.4@47.628,46.797 48.01,46.797 48.438,47.225 48.438,47.897 48.116,48.218 47.97,48.218 47.826,48.362 SB30.2@47.826,48.991
LED1': SB5.1 U5.16 | length 5.8
  Top Layer w0.152: SB5.1@90.792,47.117 90.792,50.33 91.567,51.105 U5.16@93.091,51.105
LED1_EXT: U5.1 U7.7 | length 44.3
  Top Layer w0.152: U7.7@53.9,47.453 53.9,48.041 55.186,49.327 58.057,49.327 62.019,45.364 64.643,45.364 v1(64.872,45.136) ; v1(92.201,50.571) 92.337,50.435 U5.1@92.876,50.435
  Mid-Layer 2 w0.152: v1(64.872,45.136) 66.954,47.219 71.425,47.219 73.939,49.733 91.745,49.733 92.196,50.184 v1@92.196,50.522
LED2': SB6.1 U5.4 | length 4.4
  Top Layer w0.152: SB6.1@90.792,45.695 91.338,46.241 91.338,47.541 92.876,49.079 U5.4@92.876,49.235
LED2_EXT: U5.5 U7.8 | length 45.6
  Top Layer w0.152: U7.8@53.5,47.453 53.5,48.073 55.059,49.632 58.183,49.632 62.146,45.669 65.1,45.669 v1(65.634,45.136) ; v1(92.735,47.93) 93.101,48.295 U5.5@93.101,48.61
  Mid-Layer 2 w0.152: v1(65.634,45.136) 67.412,46.914 71.551,46.914 74.066,49.428 90.81,49.428 92.309,47.93 v1(92.735,47.93)
LED3': SB7.1 U5.8 | length 6
  Top Layer w0.152: SB7.1@90.792,44.272 91.161,44.272 94.301,47.412 U5.8@94.301,48.61
LED3_EXT: U5.9 U7.9 | length 50.6
  Top Layer w0.152: U7.9@53.15,46.832 53.15,48.164 54.923,49.936 58.309,49.936 62.272,45.974 65.557,45.974 v1(66.396,45.136) ; U5.9@94.526,49.235 95.113,49.235 v1(95.275,49.073)
  Mid-Layer 2 w0.152: v1(66.396,45.136) 67.869,46.609 71.677,46.609 74.192,49.124 90.684,49.124 92.411,47.396 94.539,47.396 95.275,48.133 v1(95.275,49.073)
LED4': SB8.1 U5.12 | length 10.7
  Top Layer w0.152: SB8.1@90.817,42.838 91.415,43.436 91.415,44.095 95.809,48.489 95.809,50.063 95.437,50.435 U5.12@94.526,50.435
LED4_EXT: U5.13 U7.10 | length 54.9
  Top Layer w0.152: U7.10@53.275,46.428 52.982,46.428 52.703,46.706 52.703,48.149 54.796,50.241 58.436,50.241 62.398,46.279 66.015,46.279 v1(67.158,45.136) ; U5.13@94.301,51.06 v1@95.27,51.06
  Mid-Layer 2 w0.152: v1(67.158,45.136) 68.326,46.304 71.804,46.304 74.318,48.819 90.557,48.819 92.285,47.092 94.665,47.092 95.809,48.235 95.809,50.521 v1(95.275,51.054)
NetC3_2: C3.2 L1.1 U1.30 | length 2.2
  Top Layer w0.229: U1.30@85.46,32.011 85.935,32.011 86.245,31.701 C3.2@86.634,31.701
  Top Layer w0.508: C3.2@86.626,31.706 L1.1@87.523,31.706
NetC11_2: C11.2 SB2.1 X2.1 | length 15.3
  Top Layer w0.152: v1(73.965,41.554) 73.748,41.338 73.748,33.211 74.421,32.539 X2.1@74.819,32.539 74.907,32.627 C11.2@76.241,32.627 ; SB2.1@75.717,42.951 v1(76.581,42.951)
  Bottom Layer w0.152: v1(73.965,41.554) 75.184,41.554 v1(76.581,42.951)
NetC12_2: C12.2 SB1.1 X2.2 | length 15
  Top Layer w0.152: SB1.1@73.558,42.951 73.431,42.824 73.431,31.013 74.406,30.039 X2.2@74.819,30.039 75.319,29.539 C12.2@75.319,28.977
NetC19_2: C19.2 J2.6@1.944,28.44 J2.6@1.944,30.54 J2.6@1.944,32.94 J2.6@1.944,35.04 J2.6@4.394,28.54 J2.6@4.394,34.94 R12.2 | length 14
  Top Layer w0.508: C19.2@2.087,25.999 2.087,28.424 J2.6@2.071,28.44 ; J2.6@4.521,28.54 4.421,28.44 J2.6@2.071,28.44 ; J2.6@4.521,34.94 4.421,35.04 2.071,35.04 2.071,32.94 2.071,30.54 J2.6@2.071,28.44
NetC30_2: C30.2 SB28.1 U2.47 | length 4.3
  Top Layer w0.152: U2.47@39.899,32.43 40.784,32.43 41.494,33.139 C30.2@41.494,33.196 43.509,33.196 43.861,33.196 SB28.1@43.866,33.2
NetC37_2: C37.2 R17.2 U2.78 | length 4.1
  Top Layer w0.254: C37.2@20.97,32.138 21.859,32.138 22.651,32.93 U2.78@24.749,32.93
NetD3_1: D3.1 R33.1 R40.2 U4.1 | length 63.7
  Top Layer w0.152: v1(53.086,31.471) 53.086,34.551 50.96,36.677 50.96,39.923 51.798,40.761 52.484,40.761 52.484,41.507 D3.1@52.29,41.701 53.077,42.488 57.064,42.488 58.055,43.479 58.055,44.694 R33.1@57.521,45.228 ; v1(71.018,15.748) 71.857,15.748 71.958,15.85 82.517,15.85 83.395,14.971 U4.1@83.395,14.338
  Mid-Layer 2 w0.152: v1(53.086,31.471) 53.521,31.036 53.521,22.218 56.212,19.527 66.3,19.527 70.079,15.748 v1(71.018,15.748)
NetD4_1: D4.1 R34.1 R41.2 U4.5 | length 61.9
  Top Layer w0.152: R41.2@52.445,38 51.697,37.252 51.697,36.372 53.848,34.221 v1(53.848,31.471) ; R41.2@52.461,37.993 52.461,38.764 D4.1@52.292,38.932 52.775,39.415 53.907,39.415 54.135,39.644 54.135,40.964 55.05,41.879 57.323,41.879 58.664,43.22 58.664,45.414 57.784,46.295 R34.1@57.521,46.295 ; v1(72.536,15.011) 81.026,15.011 81.57,14.467 U4.5@81.57,14.113
  Mid-Layer 2 w0.152: v1(53.848,31.471) 53.826,31.448 53.826,22.344 56.33,19.84 66.459,19.84 70.013,16.286 71.262,16.286 v1(72.536,15.011)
